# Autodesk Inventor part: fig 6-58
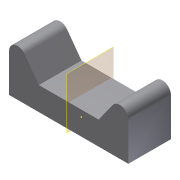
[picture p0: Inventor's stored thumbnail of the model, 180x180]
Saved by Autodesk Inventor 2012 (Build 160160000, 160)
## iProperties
Created: 2011-07
Part Number: fig 6-58
Material: Default
Document SubType Name: Modeling
Designer: CadCim
Density: 1 g/cm^3
Author: CadCim
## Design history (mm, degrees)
sketch "Sketch1"
  geometry: 1 further point
sketch "Sketch2"
  geometry: L1 (3, -4)-(17, -4); L2 (17, -4)-(17, 7); L3 (17, 7)-(14, 7); L4 (14, 7)-(10, 1.5); L5 (10, 1.5)-(3, 1.5); L6 (3, -4)-(-11, -4); L7 (-11, -4)-(-11, 7); L8 (-11, 7)-(-8, 7); L9 (-8, 7)-(-4, 1.5); L10 (-4, 1.5)-(3, 1.5); 1 further point
  constraints: 20 end point, 2 parallel, 1 perpendicular
extrude "Extrusion1" new body sketch "Sketch2" distance "d0" = 10; taper "d1" = 0 deg
fillet "Fillet1" dims "d2" = 2
workplane "Work Plane1"
mirror "Mirror1"
body "Solid1"
